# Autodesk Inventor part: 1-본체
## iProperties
Created: 2015-04
Part Number: 1-본체
Document SubType Name: Modeling
Designer: Administrator
Density: 2.71 g/cm^3
Material: 알루미늄-6061
Mass: 1108.89 g
Surface Area: 1018.61 cm^2
Volume: 409.185 cm^3
Author: Administrator
